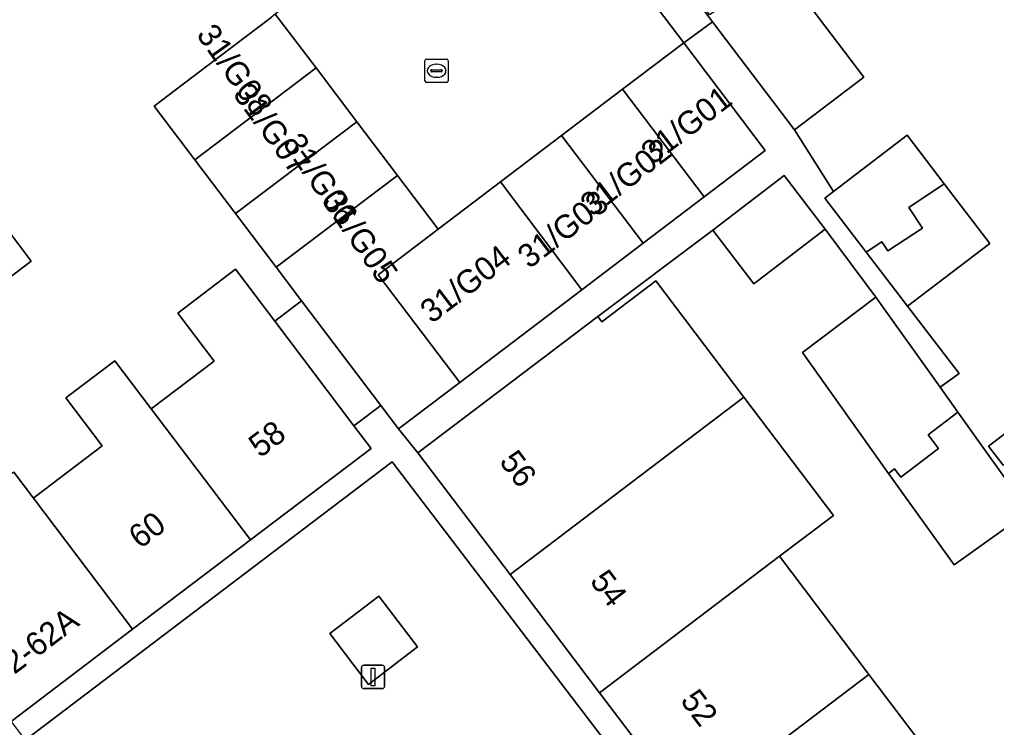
# Model space of a CAD drawing. Extents: x 160030 to 160839, y 385325 to 386450.
# Drawn here: x 160365.28 to 160407.07, y 385900.48 to 385930.74 of the extents above; entities that cross this region are included whole.
import ezdxf

# ---------------------------------------------------------------- set-up
doc = ezdxf.new("R2010")
doc.units = 0
for name, color, linetype in [('IMGEO_Erf', 7, 'Continuous'), ('IMGEO_Groenvoorziening', 7, 'Continuous'), ('IMGEO_Haag', 7, 'Continuous'), ('IMGEO_Kolk', 7, 'Continuous'), ('IMGEO_Lichtmast', 7, 'Continuous'), ('IMGEO_Pand', 7, 'Continuous'), ('IMGEO_Pand_nummerreeks', 7, 'Continuous'), ('IMGEO_Rijbaan_lokaal_open', 7, 'Continuous'), ('IMGEO_Voetpad_open', 7, 'Continuous')]:
    doc.layers.add(name, color=color, linetype=linetype)

msp = doc.modelspace()

# ---------------------------------------------------------------- linework, layer by layer
at = {"layer": 'IMGEO_Erf'}
for points in [[(160397.21, 385933.811), (160401.405, 385928.278), (160398.429, 385926.022), (160400.102, 385923.388), (160403.251, 385925.797), (160404.843, 385923.715), (160405.071, 385923.418), (160406.788, 385921.172), (160403.274, 385918.484), (160405.475, 385915.606), (160404.665, 385915.026), (160405.429, 385913.959), (160408.463, 385909.72), (160405.264, 385907.43), (160402.463, 385911.344), (160398.771, 385916.503), (160401.907, 385918.88), (160399.744, 385921.783), (160396.69, 385919.447), (160394.937, 385921.739), (160390.021, 385918.047), (160390.194, 385917.819), (160392.502, 385919.568), (160396.266, 385914.604), (160400.098, 385909.549), (160397.789, 385907.799), (160401.62, 385902.746), (160405.452, 385897.691)], [(160365.032, 385911.396), (160365.875, 385910.283), (160365.965, 385910.351), (160368.823, 385912.518), (160367.269, 385914.568), (160369.362, 385916.154), (160370.916, 385914.104), (160373.61, 385916.146), (160372.056, 385918.197), (160374.52, 385920.065), (160376.199, 385917.85), (160377.35, 385918.722), (160376.267, 385920.151), (160374.525, 385922.448), (160372.784, 385924.745), (160371.043, 385927.042), (160372.24, 385927.95), (160376.048, 385930.836)], [(160407.361, 385911.692), (160406.74, 385912.503), (160410.254, 385915.191)]]:
    msp.add_lwpolyline(points, dxfattribs=at)
msp.add_lwpolyline([(160361.186, 385920.418), (160364.103, 385922.63), (160365.781, 385920.417), (160362.863, 385918.205)], close=True, dxfattribs=at)
at = {"layer": 'IMGEO_Groenvoorziening'}
msp.add_lwpolyline([(160380.213, 385902.324), (160382.313, 385903.927), (160380.654, 385906.1), (160378.555, 385904.498)], close=True, dxfattribs=at)
at = {"layer": 'IMGEO_Haag'}
msp.add_lwpolyline([(160380.213, 385902.324), (160382.313, 385903.927), (160380.654, 385906.1), (160378.555, 385904.498)], close=True, dxfattribs=at)
at = {"layer": 'IMGEO_Kolk'}
for p, q in [((160382.623, 385928.127), (160382.623, 385928.979)), ((160382.698, 385929.053), (160383.55, 385929.053)), ((160383.624, 385928.979), (160383.624, 385928.127)), ((160382.882, 385928.547), (160382.882, 385928.559)), ((160382.925, 385928.596), (160383.323, 385928.596)), ((160383.111, 385928.833), (160383.136, 385928.833)), ((160383.366, 385928.559), (160383.366, 385928.547)), ((160383.32, 385928.51), (160382.922, 385928.51)), ((160383.134, 385928.273), (160383.109, 385928.273)), ((160383.55, 385928.053), (160382.698, 385928.053))]:
    msp.add_line(p, q, dxfattribs=at)
for points in [[(160382.623, 385928.127), (160382.623, 385928.979)], [(160382.698, 385929.053), (160383.55, 385929.053)], [(160383.624, 385928.979), (160383.624, 385928.127)], [(160383.55, 385928.053), (160382.698, 385928.053)]]:
    msp.add_lwpolyline(points, dxfattribs=at)
for centre, radius, start, end in [((160382.7, 385928.977), 0.0765, 91.552, 178.448), ((160382.7, 385928.977), 0.0765, 91.552, 178.448), ((160383.548, 385928.977), 0.0765, 1.552, 88.448), ((160383.548, 385928.977), 0.0765, 1.552, 88.448), ((160382.922, 385928.556), 0.0403, 85.8775, 175.7526), ((160382.919, 385928.546), 0.0366, 178.938, 274.7102), ((160383.323, 385928.553), 0.043, 264.8664, 352.4533), ((160383.327, 385928.558), 0.0386, 1.7309, 96.639), ((160382.7, 385928.129), 0.0765, 181.552, 268.448), ((160382.7, 385928.129), 0.0765, 181.552, 268.448), ((160383.548, 385928.129), 0.0765, 271.552, 358.448), ((160383.548, 385928.129), 0.0765, 271.552, 358.448)]:
    msp.add_arc(centre, radius, start, end, dxfattribs=at)
for centre, major_axis, ratio, start_param, end_param in [((160383.11, 385928.553), (-0.387, 0.002), 0.722429, 4.712389, 7.853982), ((160383.135, 385928.553), (-0.39, 0.002), 0.717154, 1.570796, 4.712389)]:
    msp.add_ellipse(centre, major_axis=major_axis, ratio=ratio, start_param=start_param, end_param=end_param, dxfattribs=at)
at = {"layer": 'IMGEO_Lichtmast'}
for p, q in [((160379.91, 385902.244), (160379.91, 385903.044)), ((160379.91, 385903.044), (160379.91, 385902.244)), ((160380.01, 385903.144), (160380.8, 385903.144)), ((160380.8, 385903.144), (160380.01, 385903.144)), ((160380.9, 385903.044), (160380.9, 385902.244)), ((160380.9, 385902.244), (160380.9, 385903.044)), ((160380.8, 385902.144), (160380.01, 385902.144)), ((160380.01, 385902.144), (160380.8, 385902.144))]:
    msp.add_line(p, q, dxfattribs=at)
msp.add_lwpolyline([(160380.33, 385903.019), (160380.48, 385903.019), (160380.48, 385902.269), (160380.33, 385902.269), (160380.33, 385903.019)], dxfattribs=at)
for centre, start, end in [((160380.01, 385903.044), 90, 180), ((160380.01, 385903.044), 90, 180), ((160380.8, 385903.044), 0, 90), ((160380.8, 385903.044), 360, 90), ((160380.01, 385902.244), 180, 270), ((160380.01, 385902.244), 180, 270), ((160380.8, 385902.244), 270, 0), ((160380.8, 385902.244), 270, 0)]:
    msp.add_arc(centre, 0.1, start, end, dxfattribs=at)
at = {"layer": 'IMGEO_Pand'}
for points in [[(160397.21, 385933.811), (160395.688, 385932.806), (160396.271, 385931.924), (160394.794, 385930.948), (160394.54, 385931.332), (160394.449, 385931.272), (160394.923, 385930.647), (160398.429, 385926.022), (160401.405, 385928.278)], [(160371.043, 385927.042), (160372.784, 385924.745), (160377.965, 385928.673), (160376.224, 385930.97), (160376.048, 385930.836), (160372.24, 385927.95)], [(160393.694, 385929.746), (160391.08, 385927.764), (160394.57, 385923.159), (160397.185, 385925.141)], [(160374.525, 385922.448), (160379.706, 385926.376), (160377.965, 385928.673), (160372.784, 385924.745)], [(160394.57, 385923.159), (160391.08, 385927.764), (160388.465, 385925.782), (160391.956, 385921.177)], [(160376.267, 385920.151), (160381.448, 385924.079), (160379.706, 385926.376), (160374.525, 385922.448)], [(160389.342, 385919.195), (160391.956, 385921.177), (160388.465, 385925.782), (160385.851, 385923.8)], [(160404.843, 385923.715), (160403.251, 385925.797), (160400.102, 385923.388), (160399.737, 385923.109), (160401.507, 385920.796), (160402.174, 385921.236), (160402.428, 385920.852), (160403.905, 385921.828), (160403.322, 385922.71)], [(160380.622, 385919.836), (160383.189, 385921.782), (160381.448, 385924.079), (160376.267, 385920.151), (160377.35, 385918.722), (160380.741, 385914.248), (160381.498, 385913.249), (160384.113, 385915.231)], [(160394.937, 385921.739), (160396.69, 385919.447), (160399.744, 385921.783), (160397.991, 385924.074)], [(160385.851, 385923.8), (160383.189, 385921.782), (160380.622, 385919.836), (160384.113, 385915.231), (160386.727, 385917.213), (160389.342, 385919.195)], [(160401.507, 385920.796), (160403.274, 385918.484), (160406.788, 385921.172), (160405.071, 385923.418), (160404.843, 385923.715), (160403.322, 385922.71), (160403.905, 385921.828), (160402.428, 385920.852), (160402.174, 385921.236)], [(160361.186, 385920.418), (160362.863, 385918.205), (160365.781, 385920.417), (160364.103, 385922.63)], [(160376.199, 385917.85), (160374.52, 385920.065), (160372.056, 385918.197), (160373.61, 385916.146), (160370.916, 385914.104), (160375.161, 385908.502), (160380.32, 385912.412), (160379.59, 385913.376)], [(160396.266, 385914.604), (160392.502, 385919.568), (160390.194, 385917.819), (160390.021, 385918.047), (160386.312, 385915.236), (160382.327, 385912.215), (160386.264, 385907.021)], [(160377.35, 385918.722), (160376.199, 385917.85), (160379.59, 385913.376), (160380.741, 385914.248)], [(160404.665, 385915.026), (160401.907, 385918.88), (160398.771, 385916.503), (160402.463, 385911.344), (160402.713, 385911.534), (160402.98, 385911.182), (160404.589, 385912.402), (160404.146, 385912.986), (160405.429, 385913.959)], [(160370.916, 385914.104), (160369.362, 385916.154), (160367.269, 385914.568), (160368.823, 385912.518), (160365.965, 385910.351), (160365.875, 385910.283), (160370.121, 385904.681), (160375.161, 385908.502)], [(160411.209, 385912.43), (160411.563, 385911.963), (160412.297, 385912.52), (160410.254, 385915.191), (160406.74, 385912.503), (160407.361, 385911.692), (160408.601, 385912.632), (160409.65, 385911.248)], [(160397.789, 385907.799), (160400.098, 385909.549), (160396.266, 385914.604), (160386.264, 385907.021), (160390.095, 385901.968)], [(160404.146, 385912.986), (160404.589, 385912.402), (160402.98, 385911.182), (160402.713, 385911.534), (160402.463, 385911.344), (160405.264, 385907.43), (160408.463, 385909.72), (160405.429, 385913.959)], [(160365.875, 385910.283), (160365.032, 385911.396), (160363.812, 385910.472), (160360.117, 385907.671), (160359.827, 385907.451), (160364.917, 385900.736), (160370.121, 385904.681)], [(160393.926, 385896.913), (160401.62, 385902.746), (160397.789, 385907.799), (160390.095, 385901.968)], [(160397.758, 385891.858), (160405.452, 385897.691), (160401.62, 385902.746), (160393.926, 385896.913)]]:
    msp.add_lwpolyline(points, close=True, dxfattribs=at)
at = {"layer": 'IMGEO_Rijbaan_lokaal_open'}
msp.add_lwpolyline([(160412.72, 385953.919), (160410.573, 385957.101), (160399.737, 385948.905), (160395.589, 385945.741), (160394.186, 385944.671), (160387.747, 385939.759), (160384.385, 385937.195), (160377.667, 385932.071), (160376.224, 385930.97), (160377.965, 385928.673), (160379.706, 385926.376), (160381.448, 385924.079), (160383.189, 385921.782), (160385.851, 385923.8), (160388.465, 385925.782), (160391.08, 385927.764), (160393.694, 385929.746), (160389.147, 385935.749), (160390.343, 385936.662), (160403.693, 385946.835), (160403.58, 385947.044)], close=True, dxfattribs=at)
at = {"layer": 'IMGEO_Voetpad_open'}
for points in [[(160394.449, 385931.272), (160392.725, 385933.546), (160390.343, 385936.662), (160389.147, 385935.749), (160393.694, 385929.746), (160394.923, 385930.647)], [(160399.737, 385923.109), (160400.102, 385923.388), (160398.429, 385926.022), (160394.923, 385930.647), (160393.694, 385929.746), (160397.185, 385925.141), (160394.57, 385923.159), (160391.956, 385921.177), (160389.342, 385919.195), (160386.727, 385917.213), (160384.113, 385915.231), (160381.498, 385913.249), (160382.327, 385912.215), (160386.312, 385915.236), (160390.021, 385918.047), (160394.937, 385921.739), (160397.991, 385924.074), (160399.744, 385921.783), (160401.907, 385918.88), (160404.665, 385915.026), (160405.475, 385915.606), (160403.274, 385918.484), (160401.507, 385920.796)], [(160393.926, 385896.913), (160390.095, 385901.968), (160386.264, 385907.021), (160382.327, 385912.215), (160381.498, 385913.249), (160380.741, 385914.248), (160379.59, 385913.376), (160380.32, 385912.412), (160375.161, 385908.502), (160370.121, 385904.681), (160364.917, 385900.736), (160365.521, 385899.939), (160381.217, 385911.837), (160400.882, 385886.071), (160401.696, 385886.664), (160397.758, 385891.858)], [(160381.217, 385911.837), (160365.521, 385899.939), (160385.064, 385874.105), (160385.912, 385874.747), (160391.48, 385878.959), (160400.882, 385886.071)], [(160380.213, 385902.324), (160378.555, 385904.498), (160380.654, 385906.1), (160382.313, 385903.927)]]:
    msp.add_lwpolyline(points, close=True, dxfattribs=at)

# ---------------------------------------------------------------- texts
at = {"layer": 'IMGEO_Pand_nummerreeks'}
for s, rotation, p in [('31/G08', 305.4666, (160372.817, 385930.092)), ('31/G07', 306.4711, (160374.379, 385927.545)), ('31/G01', 37.4762, (160392.368, 385924.505)), ('31/G06', 304.4634, (160376.509, 385925.443)), ('31/G02', 37.4762, (160389.768, 385922.284)), ('31/G05', 304.8757, (160378.206, 385922.962)), ('31/G03', 37.4762, (160387.087, 385920.06)), ('31/G04', 37.4762, (160382.916, 385917.717)), ('58', 37.162, (160375.574, 385911.977)), ('56', 307.1618, (160385.773, 385911.841)), ('60', 37.162, (160370.44, 385908.085)), ('54', 307.1618, (160389.647, 385906.731)), ('62-62A', 37.162, (160364.468, 385902.278)), ('52', 307.164, (160393.52, 385901.623))]:
    msp.add_text(s, height=1, rotation=rotation, dxfattribs=at).set_placement(p)

doc.saveas('drawing.dxf')
